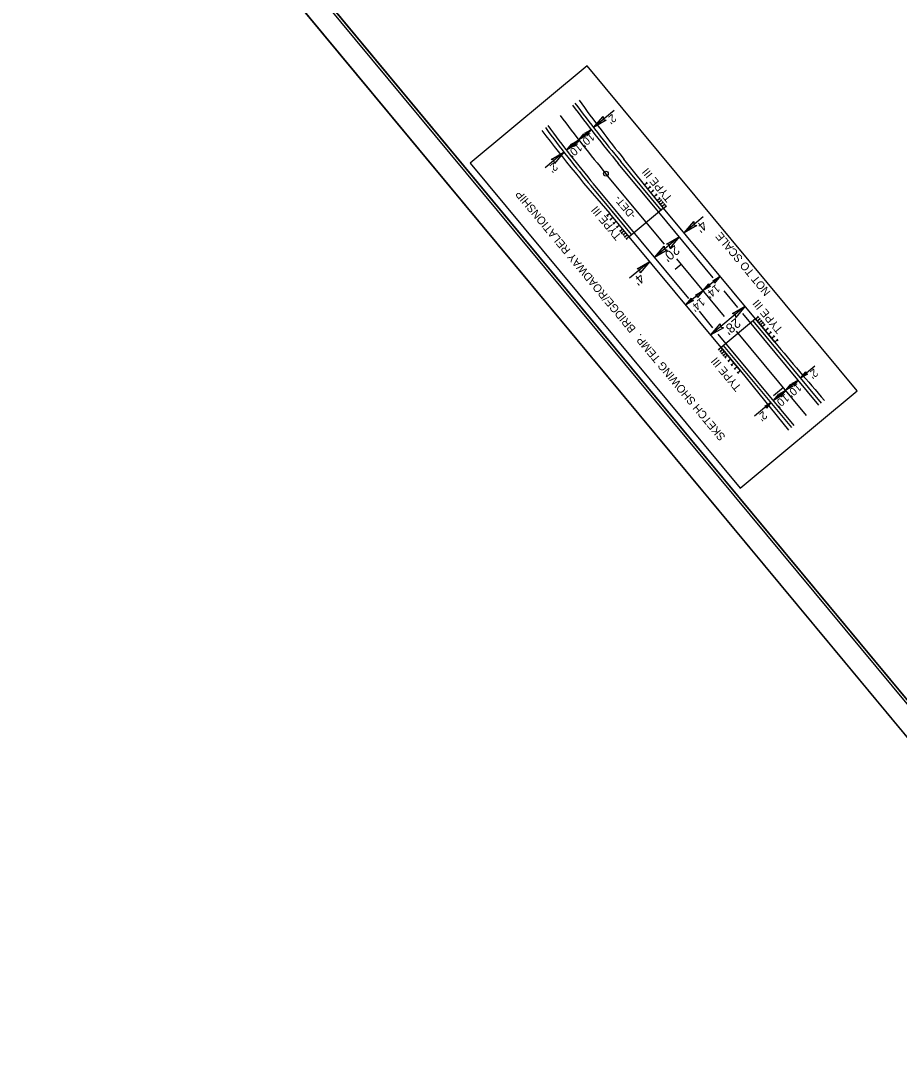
# Model space of a CAD drawing. Extents: x 2597036 to 2598995, y 852197 to 854192.
# Drawn here: x 2597077 to 2597901, y 852197 to 853163 of the extents above; entities that cross this region are included whole.
import ezdxf

# ---------------------------------------------------------------- set-up
doc = ezdxf.new("R2010")
doc.units = 0
for name, color, linetype in [('Old_Level_1', 7, 'Continuous'), ('Old_Level_2', 7, 'Continuous'), ('Prop Dimension', 7, 'Continuous'), ('Prop Dimension Text', 7, 'Continuous'), ('Prop EOT', 7, 'Continuous'), ('Prop Guardrail', 7, 'Continuous'), ('Prop Horizontal Alignment', 7, 'Continuous'), ('Prop Horizontal Alignment Direction Label', 7, 'Continuous'), ('Prop Horizontal Alignment Station Label', 7, 'Continuous'), ('Prop Horizontal Alignment Tick Large', 7, 'Continuous'), ('Prop Horizontal Alignment Tick Small', 7, 'Continuous'), ('Prop Paved Shoulder', 7, 'Continuous'), ('Prop Roadway Bridge', 7, 'Continuous'), ('Prop Structure Anchor Unit CELL', 7, 'Continuous'), ('Prop Terminator CELL', 7, 'Continuous'), ('Sheet Clip Boundary CELL', 7, 'Continuous'), ('Sheet Cutting Line CELL', 7, 'Continuous'), ('Sheet Plan CELL', 7, 'Continuous'), ('Sheet Plan Layout CELL', 7, 'Continuous'), ('Sheet Plot Border Inside CELL', 7, 'Continuous'), ('Sheet Plot Border Outside CELL', 7, 'Continuous')]:
    doc.layers.add(name, color=color, linetype=linetype)

msp = doc.modelspace()

# ---------------------------------------------------------------- linework, layer by layer
at = {"layer": 'Old_Level_1'}
for p, q in [((2597498.53, 853029.97), (2597751.39, 852725.48)), ((2597751.39, 852725.48), (2597860.97, 852816.49))]:
    msp.add_line(p, q, dxfattribs=at)
msp.add_lwpolyline([(2597860.97, 852816.49), (2597608.12, 853120.98), (2597498.53, 853029.97)], dxfattribs=at)
at = {"layer": 'Old_Level_2'}
for p, q in [((2597679.73, 852987.77), (2597661.77, 853009.41)), ((2597649.73, 852962.86), (2597631.77, 852984.49)), ((2597783.95, 852862.28), (2597765.98, 852883.91)), ((2597751.64, 852835.44), (2597733.67, 852857.08))]:
    msp.add_line(p, q, dxfattribs=at)
at = {"layer": 'Prop Dimension'}
for p, q in [((2597633.33, 853079.14), (2597614.09, 853063.17)), ((2597611.79, 853061.25), (2597588.69, 853042.08)), ((2597611.89, 853061.3), (2597600.35, 853051.72)), ((2597600.35, 853051.72), (2597600.26, 853051.64)), ((2597586.38, 853040.16), (2597568.75, 853025.52)), ((2597716.91, 852979.44), (2597699, 852964.57)), ((2597694.39, 852960.74), (2597671.31, 852941.57)), ((2597666.69, 852937.74), (2597647.84, 852922.09)), ((2597732.84, 852923.82), (2597717.2, 852910.84)), ((2597716.68, 852910.4), (2597700.53, 852896.99)), ((2597756.17, 852895.72), (2597723.86, 852868.89)), ((2597821.39, 852839.67), (2597808.03, 852828.58)), ((2597805.74, 852826.65), (2597794.2, 852817.06)), ((2597794.2, 852817.06), (2597782.66, 852807.48)), ((2597780.35, 852805.56), (2597765.01, 852792.82))]:
    msp.add_line(p, q, dxfattribs=at)
at = {"layer": 'Prop EOT'}
for p, q in [((2597675.12, 852983.94), (2597637.24, 853029.55)), ((2597703.33, 852903), (2597614.16, 853010.38)), ((2597726.09, 852922.55), (2597675.12, 852983.94)), ((2597749.41, 852894.47), (2597736.32, 852910.24)), ((2597726.01, 852875.69), (2597713.24, 852891.08)), ((2597825.23, 852803.17), (2597754.04, 852888.89)), ((2597802.15, 852784), (2597730.96, 852869.73))]:
    msp.add_line(p, q, dxfattribs=at)
for radius, start in [(1234.5, 216.48309), (1264.5, 216.55965)]:
    msp.add_arc((2598586.97, 853818.22), radius, start, 219.70669, dxfattribs=at)
at = {"layer": 'Prop Guardrail'}
for p, q in [((2597661.77, 853009.41), (2597642.57, 853033.49)), ((2597751.64, 852835.44), (2597796.88, 852779.68))]:
    msp.add_line(p, q, dxfattribs=at)
for centre, radius, start, end in [((2598616.86, 853815.8), 1249.5, 215.57151, 218.76295), ((2598597.26, 853838.98), 1292.32, 217.03826, 221.50526), ((2602575.68, 856869.37), 6246.4, 219.904128, 220.562714)]:
    msp.add_arc(centre, radius, start, end, dxfattribs=at)
at = {"layer": 'Prop Horizontal Alignment'}
for p, q in [((2597680.53, 852953.94), (2597625.7, 853019.96)), ((2597736.91, 852886.04), (2597692.03, 852940.09)), ((2597813.69, 852793.58), (2597748.09, 852872.58))]:
    msp.add_line(p, q, dxfattribs=at)
msp.add_arc((2598586.97, 853818.22), 1249.5, 216.52183, 219.70669, dxfattribs=at)
at = {"layer": 'Prop Horizontal Alignment Station Label'}
msp.add_circle((2597625.7, 853019.96), 2.25, dxfattribs=at)
at = {"layer": 'Prop Horizontal Alignment Tick Large'}
msp.add_line((2597792.05, 852819.65), (2597782.82, 852811.98), dxfattribs=at)
at = {"layer": 'Prop Horizontal Alignment Tick Small'}
for p, q in [((2597600.88, 853050.84), (2597594.96, 853046.23)), ((2597696.22, 852935.05), (2597690.45, 852930.25))]:
    msp.add_line(p, q, dxfattribs=at)
at = {"layer": 'Prop Paved Shoulder'}
for p, q in [((2597677.43, 852985.85), (2597639.55, 853031.46)), ((2597649.73, 852962.86), (2597611.86, 853008.47)), ((2597827.54, 852805.08), (2597763.67, 852882)), ((2597799.85, 852782.08), (2597735.98, 852859))]:
    msp.add_line(p, q, dxfattribs=at)
for radius, start in [(1231.5, 216.47523), (1267.5, 216.5671)]:
    msp.add_arc((2598586.97, 853818.22), radius, start, 219.70669, dxfattribs=at)
at = {"layer": 'Prop Roadway Bridge'}
for p, q in [((2597679.73, 852987.77), (2597647.42, 852960.94)), ((2597765.98, 852883.91), (2597679.73, 852987.77)), ((2597733.67, 852857.08), (2597647.42, 852960.94)), ((2597765.98, 852883.91), (2597733.67, 852857.08))]:
    msp.add_line(p, q, dxfattribs=at)
at = {"layer": 'Prop Structure Anchor Unit CELL'}
for p, q in [((2597661.77, 853009.41), (2597664.07, 853011.32)), ((2597679.73, 852987.77), (2597661.77, 853009.41)), ((2597664.62, 853010.66), (2597663.52, 853011.99)), ((2597664.76, 853005.8), (2597667.07, 853007.72)), ((2597667.62, 853007.06), (2597666.52, 853008.38)), ((2597670.61, 853003.45), (2597669.51, 853004.77)), ((2597667.75, 853002.2), (2597670.06, 853004.11)), ((2597670.75, 852998.59), (2597673.06, 853000.51)), ((2597673.61, 852999.85), (2597672.51, 853001.17)), ((2597673.74, 852994.98), (2597676.05, 852996.9)), ((2597675.24, 852993.18), (2597677.55, 852995.1)), ((2597676.6, 852996.24), (2597675.5, 852997.56)), ((2597678.1, 852994.44), (2597677, 852995.76)), ((2597676.74, 852991.38), (2597679.05, 852993.29)), ((2597678.24, 852989.57), (2597680.54, 852991.49)), ((2597679.6, 852992.63), (2597678.5, 852993.95)), ((2597679.73, 852987.77), (2597682.04, 852989.69)), ((2597681.09, 852990.83), (2597680, 852992.15)), ((2597682.59, 852989.03), (2597681.49, 852990.35)), ((2597627.69, 852980), (2597626.6, 852981.32)), ((2597629.45, 852982.58), (2597627.15, 852980.66)), ((2597647.42, 852960.94), (2597629.45, 852982.58)), ((2597630.69, 852976.39), (2597629.59, 852977.71)), ((2597632.45, 852978.97), (2597630.14, 852977.05)), ((2597633.68, 852972.79), (2597632.59, 852974.11)), ((2597635.44, 852975.36), (2597633.14, 852973.45)), ((2597636.68, 852969.18), (2597635.58, 852970.5)), ((2597638.44, 852971.76), (2597636.13, 852969.84)), ((2597639.67, 852965.57), (2597638.58, 852966.9)), ((2597641.43, 852968.15), (2597639.12, 852966.23)), ((2597642.93, 852966.35), (2597640.62, 852964.43)), ((2597641.17, 852963.77), (2597640.07, 852965.09)), ((2597642.67, 852961.97), (2597641.57, 852963.29)), ((2597644.43, 852964.55), (2597642.12, 852962.63)), ((2597644.17, 852960.16), (2597643.07, 852961.49)), ((2597645.92, 852962.74), (2597643.62, 852960.83)), ((2597645.66, 852958.36), (2597644.57, 852959.68)), ((2597647.42, 852960.94), (2597645.11, 852959.02)), ((2597765.98, 852883.91), (2597768.29, 852885.83)), ((2597765.98, 852883.91), (2597783.95, 852862.28)), ((2597767.48, 852882.11), (2597769.78, 852884.03)), ((2597767.74, 852886.49), (2597768.84, 852885.17)), ((2597768.97, 852880.31), (2597771.28, 852882.22)), ((2597769.24, 852884.69), (2597770.33, 852883.36)), ((2597770.47, 852878.5), (2597772.78, 852880.42)), ((2597770.73, 852882.88), (2597771.83, 852881.56)), ((2597772.23, 852881.08), (2597773.33, 852879.76)), ((2597773.73, 852879.28), (2597774.83, 852877.96)), ((2597771.97, 852876.7), (2597774.28, 852878.62)), ((2597774.96, 852873.09), (2597777.27, 852875.01)), ((2597776.72, 852875.67), (2597777.82, 852874.35)), ((2597777.96, 852869.49), (2597780.27, 852871.4)), ((2597779.72, 852872.06), (2597780.81, 852870.74)), ((2597780.95, 852865.88), (2597783.26, 852867.8)), ((2597782.71, 852868.46), (2597783.81, 852867.14)), ((2597783.95, 852862.28), (2597786.26, 852864.19)), ((2597785.71, 852864.85), (2597786.8, 852863.53)), ((2597730.81, 852855.82), (2597731.91, 852854.5)), ((2597733.67, 852857.08), (2597731.36, 852855.16)), ((2597732.31, 852854.02), (2597733.41, 852852.7)), ((2597735.16, 852855.28), (2597732.86, 852853.36)), ((2597733.67, 852857.08), (2597751.64, 852835.44)), ((2597733.81, 852852.22), (2597734.9, 852850.9)), ((2597736.66, 852853.47), (2597734.35, 852851.56)), ((2597735.3, 852850.42), (2597736.4, 852849.09)), ((2597738.16, 852851.67), (2597735.85, 852849.75)), ((2597736.8, 852848.61), (2597737.9, 852847.29)), ((2597739.66, 852849.87), (2597737.35, 852847.95)), ((2597739.79, 852845.01), (2597740.89, 852843.68)), ((2597742.65, 852846.26), (2597740.34, 852844.35)), ((2597742.79, 852841.4), (2597743.89, 852840.08)), ((2597745.65, 852842.66), (2597743.34, 852840.74)), ((2597745.78, 852837.79), (2597746.88, 852836.47)), ((2597748.64, 852839.05), (2597746.33, 852837.13)), ((2597748.78, 852834.19), (2597749.88, 852832.87)), ((2597751.64, 852835.44), (2597749.33, 852833.53))]:
    msp.add_line(p, q, dxfattribs=at)
at = {"layer": 'Prop Terminator CELL'}
for points in [[(2597625.97, 853070.01), (2597614.09, 853063.17), (2597623, 853073.69), (2597623.21, 853070.74)], [(2597606.76, 853055.41), (2597600.35, 853051.72), (2597605.16, 853057.4), (2597605.28, 853055.81)], [(2597605.94, 853057.86), (2597611.71, 853061.18), (2597607.38, 853056.07), (2597607.28, 853057.5)], [(2597595.22, 853045.83), (2597588.81, 853042.14), (2597593.62, 853047.82), (2597593.74, 853046.23)], [(2597593.94, 853048.03), (2597600.35, 853051.72), (2597595.54, 853046.04), (2597595.43, 853047.63)], [(2597574.51, 853033.32), (2597586.38, 853040.16), (2597577.47, 853029.64), (2597577.27, 853032.59)], [(2597710.87, 852971.4), (2597699, 852964.57), (2597707.91, 852975.09), (2597708.12, 852972.14)], [(2597682.51, 852953.9), (2597694.39, 852960.74), (2597685.47, 852950.22), (2597685.27, 852953.17)], [(2597683.18, 852948.41), (2597671.31, 852941.57), (2597680.22, 852952.09), (2597680.42, 852949.14)], [(2597654.82, 852930.9), (2597666.69, 852937.74), (2597657.78, 852927.22), (2597657.57, 852930.17)], [(2597725.72, 852919.72), (2597732.84, 852923.82), (2597727.49, 852917.51), (2597727.37, 852919.28)], [(2597709.56, 852906.3), (2597716.68, 852910.4), (2597711.34, 852904.09), (2597711.21, 852905.86)], [(2597723.81, 852914.51), (2597716.68, 852910.4), (2597722.03, 852916.72), (2597722.15, 852914.95)], [(2597707.65, 852901.09), (2597700.53, 852896.99), (2597705.87, 852903.3), (2597706, 852901.53)], [(2597744.3, 852888.89), (2597756.17, 852895.72), (2597747.26, 852885.21), (2597747.05, 852888.15)], [(2597735.73, 852875.73), (2597723.86, 852868.89), (2597732.77, 852879.41), (2597732.98, 852876.46)], [(2597814.44, 852832.27), (2597808.03, 852828.58), (2597812.84, 852834.26), (2597812.95, 852832.67)], [(2597800.61, 852820.75), (2597794.2, 852817.06), (2597799.01, 852822.74), (2597799.12, 852821.15)], [(2597799.97, 852823.32), (2597805.74, 852826.65), (2597801.4, 852821.53), (2597801.3, 852822.97)], [(2597789.07, 852811.17), (2597782.66, 852807.48), (2597787.47, 852813.16), (2597787.58, 852811.57)], [(2597787.78, 852813.37), (2597794.2, 852817.06), (2597789.38, 852811.38), (2597789.27, 852812.97)], [(2597774.58, 852802.24), (2597780.35, 852805.56), (2597776.02, 852800.45), (2597775.92, 852801.88)]]:
    msp.add_lwpolyline(points, close=True, dxfattribs=at)
at = {"layer": 'Sheet Clip Boundary CELL'}
msp.add_lwpolyline([(2598839.68, 853048.61), (2597945.27, 854125.68), (2597300.19, 853589.99), (2597421.1, 853444.38), (2597258.39, 853309.27), (2598031.89, 852377.81)], close=True, dxfattribs=at)
at = {"layer": 'Sheet Cutting Line CELL'}
msp.add_line((2597077.38, 853492.06), (2598152.9, 852196.9), dxfattribs=at)
at = {"layer": 'Sheet Plan CELL'}
for points in [[(2597105.52, 853493.36), (2598063.83, 852339.35), (2598871.63, 853010.15), (2597913.33, 854164.14)], [(2598871.63, 853010.15), (2598063.87, 852339.34), (2597233.33, 853339.43), (2597348.77, 853435.31), (2597220.99, 853589.21), (2597913.33, 854164.14)]]:
    msp.add_lwpolyline(points, close=True, dxfattribs=at)
at = {"layer": 'Sheet Plan Layout CELL'}
msp.add_lwpolyline([(2598063.87, 852339.34), (2598871.63, 853010.15), (2597913.34, 854164.13), (2597268.25, 853628.44), (2597421.1, 853444.38), (2597258.39, 853309.27)], close=True, dxfattribs=at)
at = {"layer": 'Sheet Plot Border Inside CELL'}
msp.add_lwpolyline([(2598971.62, 852893.67), (2597907.28, 854175.35), (2597095.64, 853501.37), (2598159.98, 852219.68)], close=True, dxfattribs=at)
at = {"layer": 'Sheet Plot Border Outside CELL'}
msp.add_lwpolyline([(2598995.31, 852896.45), (2597919.79, 854191.6), (2597077.38, 853492.06), (2598152.9, 852196.9)], close=True, dxfattribs=at)

# ---------------------------------------------------------------- texts
at = {"layer": 'Prop Dimension Text'}
for s, height, rotation, p in [("2'", 7.5, 219.70674, (2597631.73, 853076.37)), ("10'", 7.5, 219.70674, (2597611.39, 853058.75)), ("10'", 7.5, 219.70674, (2597599.71, 853048.88)), ("2'", 7.5, 219.70674, (2597576.82, 853030.77)), ('SKETCH SHOWING TEMP.  BRIDGE/ROADWAY RELATIONSHIP', 7.5, 129.70254, (2597738.2, 852773.68)), ("4'", 9, 219.70674, (2597715.94, 852976.69)), ('NOT TO SCALE', 7.5, 129.70254, (2597780.49, 852909.36)), ("20'", 9, 219.70674, (2597690.25, 852953.64)), ("4'", 9, 219.70674, (2597657.34, 852927.14)), ("14'", 7.5, 219.70674, (2597728.84, 852916.78)), ("14'", 7.5, 219.70674, (2597714.72, 852904.23)), ("28'", 9, 219.70674, (2597747.34, 852885.3)), ("2'", 7.5, 219.70674, (2597820.67, 852837.84)), ("10'", 7.5, 219.70674, (2597805.23, 852824.1)), ("10'", 7.5, 219.70674, (2597793.56, 852814.22)), ("2'", 7.5, 219.70674, (2597773.08, 852798.08))]:
    msp.add_text(s, height=height, rotation=rotation, dxfattribs=at).set_placement(p)
at = {"layer": 'Prop Horizontal Alignment Direction Label'}
msp.add_text('-DET-', height=7, rotation=129.70669, dxfattribs=at).set_placement((2597654.35, 852981.03))
at = {"layer": 'Prop Structure Anchor Unit CELL'}
for p in [(2597688.47, 852997.3), (2597640.83, 852961.6), (2597792.02, 852874.1), (2597753.08, 852820.04)]:
    msp.add_text('TYPE III', height=7.5, rotation=129.70669, dxfattribs=at).set_placement(p)

doc.saveas('drawing.dxf')
